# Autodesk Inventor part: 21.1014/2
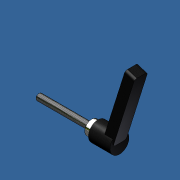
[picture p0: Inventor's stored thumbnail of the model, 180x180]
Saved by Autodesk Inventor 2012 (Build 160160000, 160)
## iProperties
Created: 2007-06
Part Number: 21.1014/2
Document SubType Name: Modeling
Designer: Andy Moles
Material: Steel
Mass: 121.251 g
Surface Area: 57.5751 cm^2
Volume: 15.4459 cm^3
Density: 7.85 g/cm^3
Description: MACHINE TO 21.1014/2
Stock Number: 21.1014/1 SLIDE LOCK
Vendor: F
Author: Andy Moles
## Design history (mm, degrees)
feature "Base1"
sketch "Sketch1"
  geometry: C1 r 6.731 at (0, 0) reference; C2 r 3 at (0, 0)
  constraints: 1 centre point, 1 coincident
  dimensions: "d0" = 6 diameter of C2
extrude "Extrusion1" join sketch "Sketch1" distance "d1" = 51; taper "d2" = 0 deg
thread "Thread1" dims "d3" = 10, "d4" = 0
chamfer "Chamfer1" distance "d5" = 0.5; stored, may be unused: second distance "d6" = 2, angle "d7" = 45 deg
body "Solid1"
other parameters: "STUD_LENGTH" = 65 [user parameter]
